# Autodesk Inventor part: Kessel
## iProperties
Created: 2007-03
Part Number: Kessel
Document SubType Name: Modeling
Designer: Benno
Manufacturer: Standard
Standards Organization: Custom
Author: Benno
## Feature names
1. Extrusion1
2. Fase1 [Chamfer]
3. Bohrung1 [Hole]
4. Bohrung2 [Hole]
5. Bohrung3 [Hole]
6. Bohrung4 [Hole]
